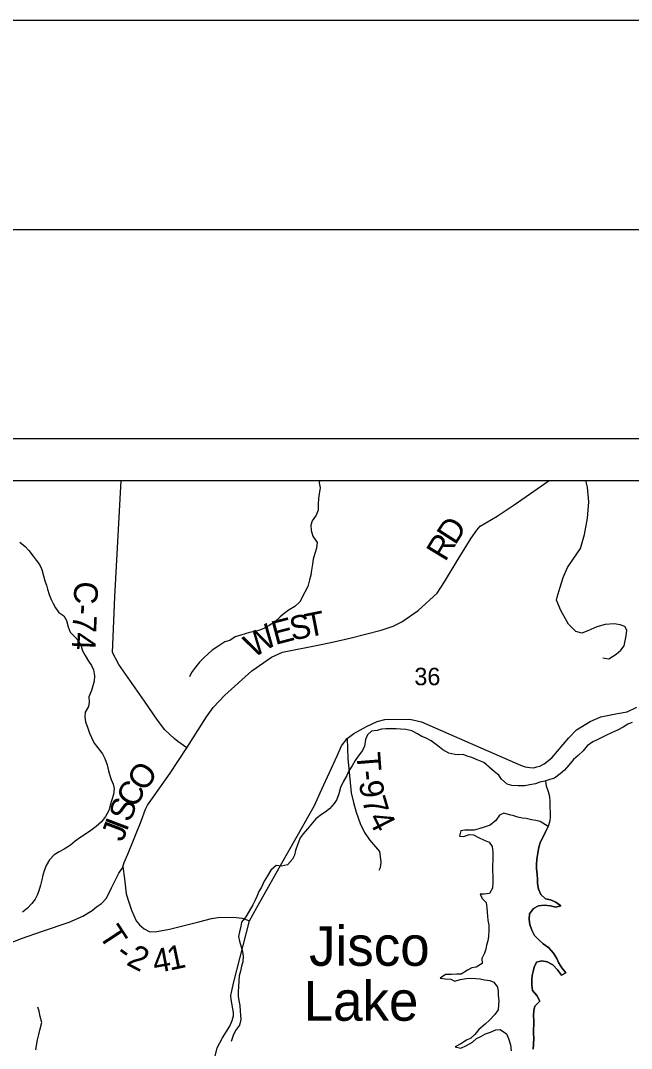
# Model space of a CAD drawing. Extents: x 0 to 34, y 0 to 22.
# Drawn here: x 3.459 to 4.921, y 19.541 to 22 of the extents above; entities that cross this region are included whole.
import ezdxf

# ---------------------------------------------------------------- set-up
doc = ezdxf.new("R2010")
doc.units = 0
for name, color, linetype in [('GM_X_City_Street', 7, 'Continuous'), ('GM_X_County_Road', 7, 'Continuous'), ('GM_X_County_Road_Text', 7, 'Continuous'), ('GM_X_Minor_Lake', 7, 'Continuous'), ('GM_X_Minor_Lake_Text', 7, 'Continuous'), ('GM_X_Minor_River', 7, 'Continuous'), ('GM_X_Section_Text', 7, 'Continuous'), ('GM_X_State_Route', 7, 'Continuous'), ('GM_X_Township_Road', 7, 'Continuous'), ('GM_X_Township_Road_Text', 7, 'Continuous'), ('SH_Border', 7, 'Continuous'), ('SH_Cut_Line', 7, 'Continuous'), ('SH_Data', 7, 'Continuous')]:
    doc.layers.add(name, color=color, linetype=linetype)

msp = doc.modelspace()

# ---------------------------------------------------------------- linework, layer by layer
at = {"layer": 'GM_X_City_Street'}
msp.add_line((3.6851, 20.6218), (3.6995, 20.9), dxfattribs=at)
at = {"layer": 'GM_X_County_Road'}
for points in [[(3.8567, 20.2605), (3.9043, 20.3345), (3.9197, 20.3564), (3.9482, 20.3858), (4.0125, 20.4444), (4.0598, 20.4771), (4.0863, 20.4891), (4.1748, 20.5069), (4.2091, 20.5135), (4.2474, 20.5227), (4.3217, 20.5418), (4.329, 20.5438), (4.351, 20.5511), (4.3718, 20.5616), (4.4104, 20.5891), (4.4562, 20.6303), (4.4738, 20.6575), (4.5065, 20.7116), (4.5373, 20.7619), (4.5509, 20.781), (4.5593, 20.7907), (4.5993, 20.8146), (4.64, 20.8417), (4.7242, 20.9)], [(3.8567, 20.2605), (3.8353, 20.2754), (3.8265, 20.2826), (3.8044, 20.303), (3.7871, 20.3264), (3.7555, 20.3716), (3.694, 20.4592), (3.6793, 20.4886), (3.6851, 20.6218)], [(3.7786, 20.1452), (3.8169, 20.1997), (3.8567, 20.2605)], [(3.7013, 19.9711), (3.7042, 19.9752), (3.707, 19.9858), (3.7159, 20.0061), (3.748, 20.0846), (3.7578, 20.1135), (3.7632, 20.1233), (3.7786, 20.1452)], [(3.3322, 19.7541), (3.4617, 19.8043), (3.5119, 19.8214), (3.5752, 19.8428), (3.6084, 19.8574), (3.6304, 19.8708), (3.6412, 19.8796), (3.6528, 19.8881), (3.6645, 19.9005), (3.6766, 19.9253), (3.6939, 19.9603), (3.7013, 19.9711)]]:
    msp.add_lwpolyline(points, dxfattribs=at)
at = {"layer": 'GM_X_Minor_Lake'}
for points in [[(4.7221, 20.0718), (4.7027, 20.0843), (4.6921, 20.0862), (4.6819, 20.0877), (4.669, 20.0908), (4.6592, 20.0923), (4.6494, 20.0946), (4.6395, 20.0973), (4.629, 20.0999), (4.6153, 20.1041), (4.6051, 20.0992), (4.5964, 20.0863), (4.5831, 20.0749), (4.5688, 20.07), (4.5559, 20.0663), (4.5449, 20.0632), (4.5332, 20.0629), (4.5226, 20.0633), (4.5128, 20.0614), (4.5097, 20.0492), (4.5196, 20.0481), (4.5324, 20.053), (4.543, 20.0519), (4.5551, 20.0458), (4.5683, 20.0389), (4.5804, 20.0348), (4.588, 20.0245), (4.5895, 20.0112), (4.5895, 20.0018), (4.5891, 19.9911), (4.5883, 19.9786), (4.5887, 19.9661), (4.589, 19.9532), (4.5894, 19.9392), (4.5882, 19.9248), (4.5814, 19.9115), (4.5689, 19.9104), (4.5591, 19.91), (4.5636, 19.8998), (4.5731, 19.8903), (4.5753, 19.8778), (4.5757, 19.8672), (4.5764, 19.8577), (4.5772, 19.8478), (4.5794, 19.8361), (4.5794, 19.8228), (4.5786, 19.8091), (4.5771, 19.7981), (4.5744, 19.7879), (4.5729, 19.7784), (4.5691, 19.769), (4.5631, 19.7565), (4.5634, 19.7443), (4.5498, 19.7356), (4.5392, 19.7337), (4.5286, 19.7281), (4.5138, 19.7186), (4.5032, 19.7186), (4.49, 19.7179), (4.4764, 19.7179), (4.4631, 19.7092), (4.4756, 19.7073), (4.4888, 19.7065), (4.4987, 19.7019), (4.5112, 19.7061), (4.5252, 19.7083), (4.5361, 19.7091), (4.549, 19.7087), (4.5588, 19.7072), (4.569, 19.7053), (4.5819, 19.7037), (4.5917, 19.6995), (4.6004, 19.6874), (4.6019, 19.6772), (4.6019, 19.6673), (4.6034, 19.6559), (4.6026, 19.6457), (4.6022, 19.6332), (4.5939, 19.6222), (4.581, 19.6086), (4.5712, 19.5995), (4.556, 19.5862), (4.5462, 19.5741), (4.5363, 19.5654), (4.5265, 19.5608), (4.5125, 19.5521), (4.4988, 19.5449), (4.5128, 19.5415), (4.5265, 19.5479), (4.5405, 19.5563), (4.5503, 19.5646), (4.5605, 19.5699), (4.5715, 19.5756), (4.5836, 19.5801), (4.5965, 19.5854), (4.6071, 19.5865), (4.6218, 19.5763), (4.6271, 19.5645), (4.6313, 19.5497), (4.6331, 19.5357)], [(4.6859, 19.5396), (4.6867, 19.551), (4.6876, 19.5665), (4.6869, 19.576), (4.6871, 19.6078), (4.6868, 19.6188), (4.6873, 19.6317), (4.6896, 19.6423), (4.7014, 19.654), (4.6943, 19.6677), (4.6842, 19.6799), (4.6824, 19.6925), (4.6829, 19.7057), (4.6837, 19.7152), (4.6856, 19.7254), (4.6884, 19.7353), (4.6937, 19.7474), (4.7066, 19.7507), (4.7195, 19.7483), (4.733, 19.741), (4.7439, 19.7288), (4.7537, 19.7166), (4.7636, 19.7219), (4.7546, 19.7337), (4.7467, 19.747), (4.7426, 19.7565), (4.7344, 19.7691), (4.7231, 19.7817), (4.7099, 19.7913), (4.7001, 19.8), (4.6889, 19.8111), (4.6825, 19.824), (4.6781, 19.8374), (4.6766, 19.8499), (4.6771, 19.8631), (4.6863, 19.876), (4.6984, 19.8823), (4.7121, 19.8838), (4.7272, 19.8825), (4.7404, 19.8787), (4.7518, 19.882), (4.7401, 19.8912), (4.7269, 19.8966), (4.7156, 19.8993), (4.7043, 19.9092), (4.6987, 19.9218), (4.6965, 19.9355), (4.6958, 19.9457), (4.6952, 19.9575), (4.6937, 19.9715), (4.6934, 19.981), (4.6943, 19.9935), (4.6959, 20.0033), (4.6974, 20.0132), (4.699, 20.0227), (4.7033, 20.0352), (4.7094, 20.0476), (4.7155, 20.0593), (4.7221, 20.0718)]]:
    msp.add_lwpolyline(points, dxfattribs=at)
at = {"layer": 'GM_X_Minor_River'}
for points in [[(4.1742, 20.9), (4.1737, 20.8945), (4.1763, 20.882), (4.1735, 20.868), (4.1719, 20.8563), (4.1714, 20.8422), (4.1714, 20.829), (4.1667, 20.8165), (4.1572, 20.8029), (4.1537, 20.793), (4.1547, 20.7798), (4.1588, 20.7668), (4.1686, 20.7512), (4.1677, 20.738), (4.1635, 20.7251), (4.1596, 20.7119), (4.1576, 20.6997), (4.1556, 20.685), (4.1536, 20.6736), (4.1505, 20.6622), (4.1467, 20.6463), (4.139, 20.6324), (4.1275, 20.6097), (4.1153, 20.5984), (4.1016, 20.5901), (4.0902, 20.5819), (4.0807, 20.5736), (4.067, 20.5611), (4.0541, 20.5525), (4.043, 20.5465), (4.0332, 20.5424), (4.0229, 20.5394), (4.0066, 20.5358), (3.9968, 20.5328), (3.9866, 20.5294), (3.9729, 20.5254), (3.9596, 20.5171), (3.9478, 20.5138), (3.9315, 20.5029), (3.9178, 20.4935), (3.9079, 20.4852), (3.8976, 20.4754), (3.887, 20.4649), (3.8778, 20.4528), (3.8683, 20.44), (3.8637, 20.4297)], [(3.4576, 20.7521), (3.4704, 20.7422), (3.4786, 20.7322), (3.4891, 20.7189), (3.4962, 20.7094), (3.5045, 20.6991), (3.5101, 20.6865), (3.5141, 20.6713), (3.5175, 20.6596), (3.5208, 20.6493), (3.5238, 20.6398), (3.5279, 20.6273), (3.5323, 20.6147), (3.5372, 20.6052), (3.5431, 20.5949), (3.5503, 20.5839), (3.5623, 20.5758), (3.5687, 20.5648), (3.5731, 20.55), (3.5776, 20.5367), (3.5892, 20.526), (3.5979, 20.5161), (3.6038, 20.5035), (3.6075, 20.4925), (3.6135, 20.4807), (3.6217, 20.4677), (3.6285, 20.4575), (3.6337, 20.4468), (3.6359, 20.4328), (3.635, 20.4199), (3.6323, 20.4085), (3.6288, 20.3975), (3.6223, 20.3824), (3.623, 20.3695), (3.6214, 20.3593), (3.6137, 20.3453), (3.6129, 20.3343), (3.6147, 20.3225), (3.6199, 20.3073), (3.624, 20.2952), (3.6288, 20.2849), (3.6355, 20.2712), (3.6438, 20.2601), (3.655, 20.2457), (3.6606, 20.2346), (3.6662, 20.2194), (3.6699, 20.2054), (3.6729, 20.194), (3.6762, 20.1841), (3.6807, 20.1731), (3.6832, 20.1628), (3.6816, 20.1488), (3.6777, 20.1355), (3.6735, 20.1227), (3.6704, 20.1105), (3.6623, 20.0958), (3.6524, 20.0834), (3.6402, 20.0717), (3.6273, 20.0623), (3.6148, 20.0536), (3.6037, 20.0461), (3.59, 20.0367), (3.5783, 20.0277), (3.5634, 20.0176), (3.5517, 20.0116), (3.5399, 20.0041), (3.5281, 19.992), (3.52, 19.9784), (3.5166, 19.9686), (3.5127, 19.9553), (3.5103, 19.9447), (3.5065, 19.9319), (3.5026, 19.9178), (3.4991, 19.9076), (3.4937, 19.8978), (3.4861, 19.888), (3.4754, 19.8763), (3.464, 19.8673)], [(4.9224, 20.3204), (4.9122, 20.3167), (4.9011, 20.3096), (4.8875, 20.3024), (4.8734, 20.2957), (4.8598, 20.2893), (4.8484, 20.2841), (4.8389, 20.2796), (4.8286, 20.2744), (4.8153, 20.2646)], [(4.8153, 20.2646), (4.8054, 20.2529), (4.7932, 20.2416), (4.7822, 20.2326), (4.7711, 20.219), (4.7604, 20.2066), (4.7502, 20.1979), (4.7368, 20.1874), (4.7259, 20.1848), (4.7141, 20.1803), (4.7016, 20.1778), (4.691, 20.174), (4.6781, 20.1715), (4.6656, 20.1696), (4.6501, 20.1694), (4.6349, 20.1699), (4.6232, 20.173), (4.6104, 20.1856), (4.6037, 20.1951), (4.5935, 20.2024), (4.5804, 20.2138), (4.5676, 20.2249), (4.5521, 20.2311), (4.5393, 20.2372), (4.528, 20.2403), (4.5181, 20.2442), (4.5083, 20.2435), (4.4981, 20.2439), (4.4841, 20.2474), (4.4694, 20.2555), (4.4574, 20.2647), (4.4419, 20.2773), (4.4299, 20.2831), (4.4197, 20.2873), (4.4087, 20.2938), (4.3952, 20.3007), (4.3812, 20.3039), (4.3687, 20.3051), (4.3581, 20.3055), (4.3483, 20.3056), (4.3331, 20.3053), (4.3229, 20.3046), (4.3123, 20.3017), (4.2991, 20.3002), (4.2892, 20.2912), (4.2849, 20.2798), (4.2818, 20.2643), (4.2772, 20.2541), (4.2672, 20.2405), (4.26, 20.2296), (4.2523, 20.2175), (4.2447, 20.205), (4.2397, 20.1941), (4.2313, 20.1789), (4.2247, 20.1653), (4.2208, 20.1502), (4.2158, 20.1366), (4.2097, 20.1267), (4.1983, 20.1139), (4.1884, 20.1064), (4.1789, 20.1008), (4.1659, 20.0902), (4.1541, 20.0759), (4.1461, 20.0661), (4.1351, 20.0548), (4.1282, 20.045), (4.1228, 20.0306), (4.1174, 20.0143), (4.115, 20.0037), (4.1097, 19.9939), (4.0978, 19.98), (4.0834, 19.977), (4.0706, 19.979), (4.0584, 19.9673), (4.05, 19.9537), (4.0423, 19.9413), (4.0358, 19.9269), (4.0297, 19.9167), (4.0243, 19.9042), (4.0201, 19.8944), (4.0151, 19.8842), (4.0063, 19.8691), (3.9979, 19.8558), (3.9876, 19.8434), (3.9863, 19.8332), (3.9829, 19.8199), (3.9809, 19.8089), (3.9827, 19.7975), (3.9868, 19.7842), (3.9901, 19.7732), (3.9919, 19.7618), (3.9907, 19.7486), (3.988, 19.7376), (3.9856, 19.7262), (3.9825, 19.7149), (3.9805, 19.6902), (3.98, 19.6754), (3.9799, 19.6659), (3.9814, 19.6561), (3.9835, 19.6439), (3.9846, 19.6306)], [(4.7154, 20.1808), (4.717, 20.1689), (4.7215, 20.1556), (4.7252, 20.1435), (4.7255, 20.131), (4.7254, 20.1169), (4.7265, 20.1071), (4.7264, 20.0949), (4.7256, 20.0854), (4.7221, 20.0718), (4.7155, 20.0593), (4.7094, 20.0476), (4.7033, 20.0352), (4.699, 20.0227), (4.6974, 20.0132), (4.6959, 20.0033), (4.6943, 19.9935), (4.6934, 19.981), (4.6937, 19.9715), (4.6952, 19.9575), (4.6958, 19.9457), (4.6965, 19.9355), (4.6987, 19.9218), (4.7043, 19.9092), (4.7156, 19.8993), (4.7269, 19.8966), (4.7401, 19.8912), (4.7518, 19.882), (4.7404, 19.8787), (4.7272, 19.8825), (4.7121, 19.8838), (4.6984, 19.8823), (4.6863, 19.876), (4.6771, 19.8631), (4.6766, 19.8499), (4.6781, 19.8374), (4.6825, 19.824), (4.6889, 19.8111), (4.7001, 19.8), (4.7099, 19.7913), (4.7231, 19.7817), (4.7344, 19.7691), (4.7426, 19.7565), (4.7467, 19.747), (4.7546, 19.7337), (4.7636, 19.7219), (4.7537, 19.7166), (4.7439, 19.7288), (4.733, 19.741), (4.7195, 19.7483), (4.7066, 19.7507), (4.6937, 19.7474), (4.6884, 19.7353), (4.6856, 19.7254), (4.6837, 19.7152), (4.6829, 19.7057), (4.6824, 19.6925), (4.6842, 19.6799), (4.6943, 19.6677), (4.7014, 19.654), (4.6896, 19.6423), (4.6873, 19.6317), (4.6868, 19.6188), (4.6871, 19.6078), (4.6869, 19.576), (4.6876, 19.5665), (4.6867, 19.551), (4.6859, 19.5396)], [(3.4958, 19.5375), (3.497, 19.5481), (3.4994, 19.5614), (3.5029, 19.5742), (3.506, 19.5883), (3.5099, 19.603), (3.5058, 19.6178), (3.5037, 19.6304), (3.5003, 19.6399)], [(3.9846, 19.6306), (3.9853, 19.6204), (3.9863, 19.6105), (3.9828, 19.5969), (3.9733, 19.5841), (3.9675, 19.572), (3.9633, 19.558)]]:
    msp.add_lwpolyline(points, dxfattribs=at)
at = {"layer": 'GM_X_State_Route'}
for points in [[(4.1459, 20.0928), (4.1618, 20.121), (4.1802, 20.1611), (4.2164, 20.2408), (4.227, 20.2653), (4.2409, 20.2826), (4.2565, 20.2943), (4.2866, 20.3116), (4.3123, 20.3233), (4.3312, 20.3277), (4.3905, 20.3287), (4.4183, 20.3225), (4.4968, 20.2879), (4.6554, 20.2184), (4.6666, 20.2144), (4.6778, 20.2129), (4.6877, 20.2126), (4.6947, 20.2147), (4.7014, 20.2166), (4.7125, 20.222), (4.7302, 20.2365), (4.7708, 20.284), (4.7899, 20.3031), (4.8222, 20.3235), (4.8479, 20.3341), (4.8878, 20.3423), (4.9111, 20.3459), (4.934, 20.3572)], [(4.007, 19.8462), (4.0247, 19.8786), (4.0808, 19.9789), (4.1379, 20.0786), (4.1459, 20.0928)], [(3.9169, 19.4907), (3.9295, 19.5429), (3.9423, 19.5665), (3.9599, 19.5947), (3.9657, 19.6079), (3.9685, 19.6191), (3.9685, 19.6268), (3.9631, 19.658), (3.9626, 19.6674), (3.9645, 19.6792), (3.9691, 19.7002), (4.007, 19.8462)]]:
    msp.add_lwpolyline(points, dxfattribs=at)
at = {"layer": 'GM_X_Township_Road'}
for points in [[(4.8528, 20.4754), (4.8665, 20.4733), (4.8844, 20.484), (4.8959, 20.4941), (4.9038, 20.5041), (4.9081, 20.5285), (4.9103, 20.5415), (4.9053, 20.5501), (4.8938, 20.5544), (4.8794, 20.5566), (4.8579, 20.5551), (4.8378, 20.5494), (4.8169, 20.54), (4.8019, 20.5343), (4.7882, 20.5386), (4.7703, 20.5558), (4.7523, 20.5889), (4.7415, 20.6133), (4.743, 20.6205), (4.7502, 20.6442), (4.7573, 20.6679), (4.7681, 20.6915), (4.7832, 20.7138), (4.799, 20.7368), (4.809, 20.7705), (4.8162, 20.8093), (4.8191, 20.8488), (4.8155, 20.884), (4.8122, 20.9)], [(4.2409, 20.2826), (4.2426, 20.2347), (4.2504, 20.1522), (4.256, 20.1293), (4.2621, 20.1059), (4.2716, 20.0792), (4.2822, 20.058), (4.2939, 20.0402), (4.3178, 20.0118), (4.3197, 20.0004), (4.3212, 19.9865), (4.3197, 19.9729), (4.3163, 19.9667)], [(3.7042, 19.9752), (3.7077, 19.9469), (3.712, 19.9108), (3.718, 19.8906), (3.7244, 19.8722), (3.7356, 19.8466), (3.744, 19.8364), (3.7552, 19.827), (3.7683, 19.8201), (3.7851, 19.8205), (3.8157, 19.8261), (3.8856, 19.8436), (3.9161, 19.8518), (3.9312, 19.8544), (3.9676, 19.8549), (3.9894, 19.853), (4.007, 19.8462)]]:
    msp.add_lwpolyline(points, dxfattribs=at)
at = {"layer": 'SH_Border'}
msp.add_lwpolyline([(1.5, 21.5), (33.5, 21.5), (33.5, 0.5), (1.5, 0.5)], close=True, dxfattribs=at)
at = {"layer": 'SH_Cut_Line'}
msp.add_lwpolyline([(0, 0), (34, 0), (34, 22), (0, 22)], close=True, dxfattribs=at)
at = {"layer": 'SH_Data'}
for p, q in [((2, 21), (9, 21)), ((2.1, 20.9), (8.9, 20.9))]:
    msp.add_line(p, q, dxfattribs=at)

# ---------------------------------------------------------------- texts
at = {"layer": 'GM_X_County_Road_Text'}
for s, height, rotation, p in [('D', 0.0568, 57.4224, (4.4994, 20.7431)), ('R', 0.0568, 58.7149, (4.4754, 20.7035)), ('C-74', 0.05682, 267.5998, (3.5883, 20.6594)), ('T', 0.0568, 11.2139, (4.1463, 20.524)), ('W', 0.0568, 30.8413, (4.0158, 20.4739)), ('E', 0.0568, 14.662, (4.0685, 20.506)), ('S', 0.0568, 11.1841, (4.1087, 20.5166)), ('O', 0.0568, 54.7134, (3.7562, 20.1529)), ('C', 0.0568, 60.3021, (3.7339, 20.1136)), ('S', 0.0568, 69.073, (3.7212, 20.0799)), ('I', 0.0568, 69.3133, (3.713, 20.0581)), ('J', 0.0568, 69.3288, (3.7036, 20.0332))]:
    msp.add_text(s, height=height, rotation=rotation, dxfattribs=at).set_placement(p)
at = {"layer": 'GM_X_Minor_Lake_Text'}
for s, rotation, p in [('Jisco', 0.0075, (4.1496, 19.7387)), ('Lake', 0.0076, (4.1366, 19.6073))]:
    msp.add_text(s, height=0.09469, rotation=rotation, dxfattribs=at).set_placement(p)
at = {"layer": 'GM_X_Section_Text'}
msp.add_text('36', height=0.04186, rotation=0, dxfattribs=at).set_placement((4.4015, 20.4099))
at = {"layer": 'GM_X_Township_Road_Text'}
for s, rotation, p in [('T', 274.4746, (4.2628, 20.2479)), ('-', 275.6004, (4.2662, 20.2044)), ('9', 278.0322, (4.2688, 20.1787)), ('7', 286.4767, (4.2755, 20.1354)), ('4', 296.9239, (4.2896, 20.0917)), ('T', 303.3209, (3.6445, 19.8124)), ('-', 324.1437, (3.6832, 19.7607)), ('2', 332.7024, (3.7099, 19.7423)), ('4', 10.5279, (3.7804, 19.7206)), ('1', 12.0192, (3.8162, 19.7272))]:
    msp.add_text(s, height=0.0568, rotation=rotation, dxfattribs=at).set_placement(p)

doc.saveas('drawing.dxf')
